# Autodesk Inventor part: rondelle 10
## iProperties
Shininess: 20.0
Angle Display Precision: 2
Document Length Units: 11269
Document Angle Units: 11279
Document Time Units: 11290
Document Mass Units: 11283
Document Length Units Precision: 3
Document Angle Units Precision: 2
Compacted: True
Created: 2002-04
Part Number: rondelle 10
Material: Par défaut
Document SubType Name: Modélisation
Designer: thchene
Density: 0.0
Volumn: 0.0
Area: 0.0
PropertySet Name: Model Information
Control State: 0
Master: False
Checked Out: False
Author: thchene
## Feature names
1. Révolution1 [Revolution]
